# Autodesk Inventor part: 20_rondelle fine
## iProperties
Shininess: 20.0
Length Units: 11269
Angle Units: 11279
Time Units: 11290
Mass Units: 11283
Length Display Precision: 3
Angle Display Precision: 2
Created: 2000-12
Part Number: 20_rondelle fine
Material: Par défaut
Document SubType Name: Modélisation
Density: 0.0
Volumn: 0.0
Area: 0.0
PropertySet Name: Model Information
Control State: 0
Master: False
Checked Out: False
Author: Laurent GAUTHERON
